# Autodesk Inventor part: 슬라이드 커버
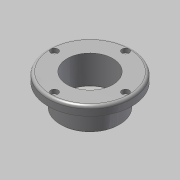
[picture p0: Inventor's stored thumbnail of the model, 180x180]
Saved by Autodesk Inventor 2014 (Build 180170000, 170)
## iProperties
Created: 2015-10
Part Number: 슬라이드 커버
Document SubType Name: Modeling
Designer: mdu
Density: 7.86 g/cm^3
Material: 강철, 연강
Mass: 598.523 g
Surface Area: 229.996 cm^2
Volume: 76.148 cm^3
Appearance: 강철
Author: mdu
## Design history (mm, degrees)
sketch "스케치1"
  geometry: C1 r 46 at (0, -39.25) reference; C2 r 32.5 at (0, -39.25) reference; 1 further point
  node "참조1"
  node "참조2"
extrude "돌출1" new body sketch "스케치1" distance "d0" = 10; taper "d1" = 0 deg
extrude "돌출2" join sketch "스케치1" distance "d2" = 25; taper "d3" = 0 deg
hole "구멍1" diameter "d6" = 50; stored, may be unused: countersink angle "d10" = 90 deg, drill point angle "d12" = 118 deg; dims "d4" = 10, "d5" = 10, "d7" = 6, "d8" = 4, "d9" = 2, "d11" = 8
sketch "스케치2"
  geometry: C1 r 46 at (0, 0) reference; C2 r 1.621 at (0, 39) reference; C3 r 1.621 at (39, 0) reference; C4 r 1.621 at (0, -39) reference; C5 r 1.621 at (-39, 0) reference; C6 r 33.5 at (0, 0) reference; 1 further point
hole "구멍2" sketch "스케치2" at (0, 39) diameter "d13" = 4.5; stored, may be unused: countersink angle "d17" = 90 deg, drill point angle "d19" = 118 deg; dims "d14" = 6, "d15" = 8, "d16" = 4.4, "d18" = 8
fillet "모깎기1" dims "d23" = 3
chamfer "모따기1" distance "d24" = 1; stored, may be unused: second distance "d25" = 2, angle "d26" = 45 deg
sketch "스케치3"
  geometry: C1 r 25 at (0, 0); C2 r 30 at (0, 0); C3 r 26 at (0, 0) reference; 1 further point
  constraints: 2 centre point, 2 coincident
  dimensions: "d27" = 60 diameter of C2
extrude "돌출3" cut sketch "스케치3" distance "d28" = 3; taper "d29" = 0 deg
chamfer "모따기2" distance "d30" = 1; stored, may be unused: second distance "d31" = 2, angle "d32" = 45 deg
node "솔리드1"
pattern_circular "원형 패턴1" dims angle "d21" = 360 deg
node "참조3"
